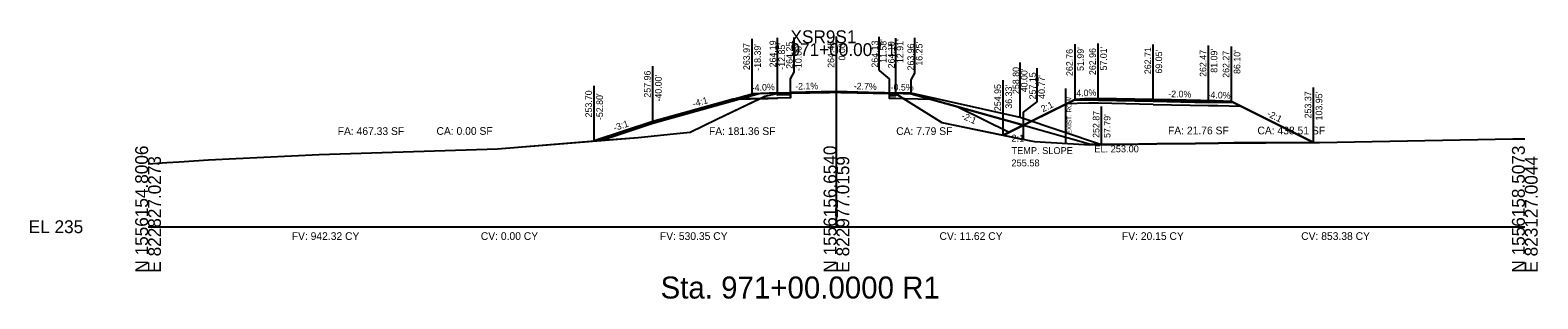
# Model space of a CAD drawing. Extents: x -26 to 823017, y -16 to 1558356.
# Drawn here: x 1974.3 to 2302.8, y 1984.3 to 2042.8 of the extents above; entities that cross this region are included whole.
import ezdxf

# ---------------------------------------------------------------- set-up
doc = ezdxf.new("R2010")
doc.units = 0
for name, color, linetype in [('1', 7, 'Continuous'), ('ASPHALT_19MM1', 7, 'Continuous'), ('ASPHALT_9_5MM1', 7, 'Continuous'), ('CONST_DCH', 7, 'Continuous'), ('CONST_LV3', 7, 'Continuous'), ('Draft_XS_Grid', 7, 'Continuous'), ('Draft_XS_Text', 7, 'Continuous'), ('DTM_CORRIDOR', 7, 'Continuous'), ('DTM_P_FINISHED_GRADE2', 7, 'Continuous'), ('DTM_X_GROUND', 7, 'Continuous'), ('SLOPE_STAKES_FILL', 7, 'Continuous'), ('X_PROFILES_1', 7, 'Continuous'), ('X_TRANS_EOP', 7, 'Continuous'), ('XS_CELL', 7, 'Continuous'), ('XS_M_SHAPES_EARTHWORK', 7, 'Continuous'), ('XS_P_ASPHALT', 7, 'Continuous'), ('XS_P_DR_GRAVEL', 7, 'Continuous'), ('XS_P_GROUND', 7, 'Continuous'), ('XS_P_NULL_POINT', 7, 'Continuous'), ('XS_P_SHOULDER', 7, 'Continuous'), ('XS_P_SUBGRADE_GRANULAR', 7, 'Continuous'), ('XS_P_SUBGRADE_LEVELING', 7, 'Continuous'), ('XS_P_SUBGRADE_MILLING', 7, 'Continuous'), ('XS_P_SUBGRADE_UNDERCUT', 7, 'Continuous'), ('XS_P_TX_CLEARZONE', 7, 'Continuous'), ('XS_P_TX_FS_BS', 7, 'Continuous'), ('XS_SHEET_EW_TX_AREA', 7, 'Continuous'), ('XS_SHEET_EW_TX_VOLUME', 7, 'Continuous'), ('XS_X_ROW', 7, 'Continuous')]:
    doc.layers.add(name, color=color, linetype=linetype)

msp = doc.modelspace()

# ---------------------------------------------------------------- linework, layer by layer
at = {"layer": '1'}
for points in [[(2140, 2029.12), (2140, 2028.95), (2137.15, 2028.9), (2137.15, 2029.06), (2140, 2029.12)], [(2161.58, 2029.01), (2161.58, 2029.01), (2161.58, 2028.84), (2161.58, 2028.84), (2161.58, 2028.84), (2162.91, 2028.81), (2162.91, 2028.81), (2162.91, 2028.97), (2161.58, 2029.01)]]:
    msp.add_lwpolyline(points, dxfattribs=at)
at = {"layer": 'ASPHALT_19MM1'}
for points in [[(2140, 2028.95), (2140, 2028.75), (2137.15, 2028.69), (2137.15, 2028.9), (2140, 2028.95)], [(2161.58, 2028.84), (2161.58, 2028.84), (2161.58, 2028.63), (2161.58, 2028.63), (2161.58, 2028.63), (2162.91, 2028.6), (2162.91, 2028.6), (2162.91, 2028.81), (2161.58, 2028.84)], [(2207.01, 2027.58), (2219.05, 2027.34), (2231.09, 2027.1), (2231.09, 2027.3), (2219.05, 2027.55), (2207.01, 2027.79), (2207.01, 2027.58)]]:
    msp.add_lwpolyline(points, dxfattribs=at)
at = {"layer": 'ASPHALT_9_5MM1'}
for points in [[(2140, 2029.25), (2140, 2029.12), (2137.15, 2029.06), (2137.15, 2029.19), (2140, 2029.25)], [(2161.58, 2029.13), (2161.58, 2029.13), (2161.58, 2029.01), (2161.58, 2029.01), (2161.58, 2029.01), (2162.91, 2028.97), (2162.91, 2028.97), (2162.91, 2029.1), (2161.58, 2029.13)]]:
    msp.add_lwpolyline(points, dxfattribs=at)
at = {"layer": 'CONST_LV3'}
for points in [[(2110, 2022.96), (2127.49, 2027.82), (2127.49, 2027.82)], [(2150, 2029.45), (2164, 2029.17)], [(2166.25, 2029.08), (2164, 2029.17), (2164, 2029.17)], [(2186.33, 2019.95), (2194.95, 2024.25), (2201.99, 2027.76), (2204.95, 2027.87), (2207.01, 2027.96)], [(2190.63, 2022.08), (2190.63, 2022.08), (2202.01, 2027.76), (2202.91, 2027.79), (2207.03, 2027.95), (2209.88, 2027.9), (2219.06, 2027.71), (2226.52, 2027.33), (2231.1, 2027.1), (2233.9, 2027.19), (2236.12, 2027.27), (2244.36, 2023.16), (2253.96, 2018.37), (2254.53, 2018.38), (2255.25, 2018.38), (2255.29, 2018.38), (2297.37, 2019.19), (2300, 2019.17)], [(2253.96, 2018.37), (2236.8, 2026.93), (2236.12, 2027.27)], [(2000, 2013.74), (2004.11, 2014), (2006.78, 2014.16), (2013.17, 2014.56), (2037.32, 2015.77), (2076.15, 2016.99), (2096.48, 2018.64), (2096.83, 2018.67), (2098.66, 2018.82)]]:
    msp.add_lwpolyline(points, dxfattribs=at)
at = {"layer": 'DTM_P_FINISHED_GRADE2'}
msp.add_lwpolyline([(2098.66, 2018.82), (2110, 2022.6), (2133.15, 2029.03), (2137.15, 2029.19), (2140, 2029.25), (2150, 2029.45), (2161.58, 2029.13), (2162.91, 2029.1), (2166.25, 2028.96), (2188.91, 2022.67), (2190.63, 2022.1)], dxfattribs=at)
at = {"layer": 'DTM_X_GROUND'}
for points in [[(2000, 2013.74), (2004.11, 2014), (2006.78, 2014.16), (2013.17, 2014.56), (2037.32, 2015.77), (2076.15, 2016.99), (2096.48, 2018.64), (2096.83, 2018.67), (2098.66, 2018.82), (2110, 2022.6), (2110, 2022.6), (2110, 2022.6), (2133.15, 2029.03), (2133.15, 2029.03), (2137.15, 2029.19), (2140, 2029.25), (2140, 2029.25), (2140, 2029.25), (2150, 2029.45), (2150, 2029.45), (2161.58, 2029.13), (2161.58, 2029.13), (2162.91, 2029.1), (2162.91, 2029.1), (2166.25, 2028.96), (2166.25, 2028.96), (2188.91, 2022.67), (2188.91, 2022.67), (2188.91, 2022.67), (2188.91, 2022.67), (2190.63, 2022.1), (2190.63, 2022.1), (2202.01, 2027.76), (2202.91, 2027.79), (2207.03, 2027.95), (2209.88, 2027.9), (2219.06, 2027.71), (2226.52, 2027.33), (2231.1, 2027.1), (2233.9, 2027.19), (2236.12, 2027.27), (2244.36, 2023.16), (2253.96, 2018.37), (2254.53, 2018.38), (2255.25, 2018.38), (2255.29, 2018.38), (2297.37, 2019.19), (2300, 2019.17)], [(2000, 2013.74), (2004.11, 2014), (2006.78, 2014.16), (2013.17, 2014.56), (2037.32, 2015.77), (2076.15, 2016.99), (2106.79, 2019.48), (2114.49, 2020.23), (2118.13, 2020.59), (2123.96, 2023.42), (2134.43, 2028.44), (2136.05, 2028.81), (2137.42, 2029.1), (2148.5, 2029.27), (2150.07, 2029.3), (2150.97, 2029.27), (2162.88, 2029.01), (2165.66, 2027.27), (2172.96, 2022.7), (2192.38, 2018.7), (2193.19, 2018.54), (2204.03, 2017.89), (2205.06, 2017.83), (2219.81, 2018.04), (2228.22, 2018.16), (2233.23, 2018.23), (2236.57, 2018.28), (2255.29, 2018.38), (2297.37, 2019.19), (2300, 2019.17)], [(2000, 2013.74), (2004.11, 2014), (2006.78, 2014.16), (2013.17, 2014.56), (2037.32, 2015.77), (2076.15, 2016.99), (2106.79, 2019.48), (2114.49, 2020.23), (2118.13, 2020.59), (2123.96, 2023.42), (2134.43, 2028.44), (2136.05, 2028.81), (2137.42, 2029.1), (2148.5, 2029.27), (2150.07, 2029.3), (2150.97, 2029.27), (2162.88, 2029.01), (2165.66, 2027.27), (2172.96, 2022.7), (2185.67, 2020.09), (2186.34, 2019.95), (2186.98, 2020.26), (2202.01, 2027.76), (2202.91, 2027.79), (2207.03, 2027.95), (2209.88, 2027.9), (2219.06, 2027.71), (2226.52, 2027.33), (2231.1, 2027.1), (2233.9, 2027.19), (2236.12, 2027.27), (2244.36, 2023.16), (2253.96, 2018.37), (2254.53, 2018.38), (2255.25, 2018.38), (2255.29, 2018.38), (2297.37, 2019.19), (2300, 2019.17)]]:
    msp.add_lwpolyline(points, dxfattribs=at)
at = {"layer": 'X_TRANS_EOP'}
msp.add_lwpolyline([(2207.01, 2027.79), (2219.05, 2027.55), (2231.09, 2027.3), (2231.09, 2027.47), (2219.05, 2027.71), (2207.01, 2027.96), (2207.01, 2027.79)], dxfattribs=at)
at = {"layer": 'XS_CELL'}
for p, q in [((2150, 2000), (2150, 2040)), ((2000, 2000), (2150, 2000)), ((2150, 2000), (2300, 2000))]:
    msp.add_line(p, q, dxfattribs=at)
at = {"layer": 'XS_M_SHAPES_EARTHWORK'}
for points in [[(2097.2, 2018.7), (2106.79, 2019.48), (2114.49, 2020.23), (2118.13, 2020.59), (2123.96, 2023.42), (2133.4, 2027.94), (2127.49, 2027.82), (2110, 2022.96)], [(2133.4, 2027.94), (2134.43, 2028.44), (2136.05, 2028.81), (2137.42, 2029.1), (2143.9, 2029.2), (2140, 2029.12), (2140, 2028.95), (2140, 2028.75), (2140, 2028.08), (2137.15, 2028.02), (2135.15, 2027.98)], [(2156.28, 2029.15), (2162.88, 2029.01), (2164.68, 2027.88), (2162.91, 2027.93), (2161.58, 2027.97), (2161.58, 2028.63), (2161.58, 2028.84), (2161.58, 2029.01), (2156.87, 2029.14)], [(2164.68, 2027.88), (2165.66, 2027.27), (2172.96, 2022.7), (2190.77, 2019.03), (2190.77, 2022.15), (2170.74, 2027.72), (2164.91, 2027.88)]]:
    msp.add_lwpolyline(points, close=True, dxfattribs=at)
at = {"layer": 'XS_P_ASPHALT'}
msp.add_lwpolyline([(2140, 2029.12), (2140, 2029.12), (2140, 2029.12), (2150, 2029.33), (2150, 2029.33), (2161.58, 2029.01), (2161.58, 2029.01), (2161.58, 2029.13), (2150, 2029.45), (2150, 2029.45), (2140, 2029.25), (2140, 2029.25), (2140, 2029.12)], dxfattribs=at)
at = {"layer": 'XS_P_DR_GRAVEL'}
for points in [[(2204.95, 2027.87), (2201.99, 2027.76), (2201.93, 2027.73), (2201.85, 2027.68), (2203.99, 2027.64), (2207.01, 2027.58), (2207.01, 2027.8), (2207.01, 2027.96), (2204.95, 2027.87)], [(2232.55, 2027.41), (2236.1, 2027.27), (2236.26, 2027.19), (2236.68, 2026.98), (2232.71, 2027.06), (2231.09, 2027.1), (2231.09, 2027.36), (2231.09, 2027.47), (2232.55, 2027.41)]]:
    msp.add_lwpolyline(points, dxfattribs=at)
at = {"layer": 'XS_P_GROUND'}
msp.add_line((2176.59, 2026.09), (2187.61, 2020.58), dxfattribs=at)
for points in [[(2097.2, 2018.7), (2110, 2022.96), (2110, 2022.96), (2131.61, 2028.97), (2131.61, 2028.97)], [(2207.79, 2017.87), (2190, 2023.8), (2190, 2023.8), (2166.25, 2029.08), (2166.25, 2029.08)], [(2190.77, 2022.15), (2166.25, 2028.96), (2166.25, 2028.96)], [(2201.99, 2027.76), (2186.33, 2019.95)], [(2236.1, 2027.27), (2253.95, 2018.37)], [(2253.96, 2018.37), (2253.96, 2018.37), (2236.57, 2018.28), (2236.57, 2018.28), (2236.57, 2018.28), (2233.23, 2018.23), (2228.22, 2018.16), (2228.22, 2018.16), (2219.81, 2018.04), (2219.81, 2018.04), (2207.79, 2017.87), (2207.79, 2017.87), (2207.79, 2017.87)], [(2253.96, 2018.37), (2253.96, 2018.37), (2236.57, 2018.28), (2236.57, 2018.28), (2236.57, 2018.28), (2233.23, 2018.23), (2228.22, 2018.16), (2228.22, 2018.16), (2219.81, 2018.04), (2219.81, 2018.04), (2207.79, 2017.87), (2207.79, 2017.87), (2207.79, 2017.87)]]:
    msp.add_lwpolyline(points, dxfattribs=at)
at = {"layer": 'XS_P_SHOULDER'}
for points in [[(2137.15, 2029.19), (2131.61, 2028.97)], [(2162.91, 2029.1), (2166.25, 2028.96)], [(2201.99, 2027.76), (2204.95, 2027.87), (2207.01, 2027.96)], [(2236.1, 2027.27), (2232.55, 2027.41), (2231.09, 2027.47)]]:
    msp.add_lwpolyline(points, dxfattribs=at)
at = {"layer": 'XS_P_SUBGRADE_GRANULAR'}
for points in [[(2127.49, 2027.82), (2135.15, 2027.98), (2135.15, 2027.98), (2137.15, 2028.02), (2137.15, 2028.02)], [(2140, 2028.08), (2137.15, 2028.02)], [(2140, 2028.08), (2140, 2029.25)], [(2161.58, 2027.97), (2161.58, 2029.13)], [(2162.91, 2027.93), (2161.58, 2027.97), (2161.58, 2027.97)], [(2170.74, 2027.72), (2164.91, 2027.88), (2164.91, 2027.88), (2162.91, 2027.93), (2162.91, 2027.93)], [(2207.01, 2026.91), (2205, 2026.95), (2199.98, 2026.75)], [(2219.05, 2026.67), (2207.01, 2026.91)], [(2219.05, 2026.67), (2231.09, 2026.43)], [(2231.09, 2026.43), (2233.09, 2026.39), (2238.07, 2026.29)]]:
    msp.add_lwpolyline(points, dxfattribs=at)
at = {"layer": 'XS_P_SUBGRADE_LEVELING'}
for points in [[(2140, 2029.12), (2140, 2029.12), (2148.5, 2029.3), (2148.5, 2029.3), (2150, 2029.33), (2150.07, 2029.32), (2150.97, 2029.3), (2150.97, 2029.3), (2161.58, 2029.01), (2161.58, 2029.01)], [(2140, 2029.12), (2140, 2029.12), (2143.9, 2029.2), (2143.9, 2029.2), (2148.5, 2029.27), (2150, 2029.29), (2150.07, 2029.3), (2150.97, 2029.27), (2156.28, 2029.15), (2156.28, 2029.15), (2161.58, 2029.01), (2161.58, 2029.01)]]:
    msp.add_lwpolyline(points, dxfattribs=at)
at = {"layer": 'XS_P_SUBGRADE_MILLING'}
msp.add_lwpolyline([(2161.58, 2029.04), (2161.58, 2029.04), (2161.58, 2029.01), (2161.58, 2029.01), (2161.58, 2029.01), (2156.28, 2029.15), (2156.28, 2029.15), (2150.97, 2029.27), (2150.07, 2029.3), (2150, 2029.29), (2148.5, 2029.27), (2143.9, 2029.2), (2143.9, 2029.2), (2140, 2029.12), (2140, 2029.12), (2140, 2029.14), (2140, 2029.14), (2148.5, 2029.27), (2148.5, 2029.27), (2150, 2029.29), (2150.07, 2029.3), (2150.97, 2029.27), (2150.97, 2029.27), (2161.58, 2029.04)], dxfattribs=at)
at = {"layer": 'XS_P_SUBGRADE_UNDERCUT'}
msp.add_lwpolyline([(2205.39, 2018), (2219.81, 2018.04), (2228.22, 2018.16), (2233.23, 2018.23), (2253.95, 2018.37), (2236.1, 2027.27), (2232.55, 2027.41), (2223.03, 2027.63), (2219.05, 2027.71), (2214.59, 2027.8), (2207.01, 2027.96), (2204.07, 2027.84), (2201.99, 2027.76), (2190.77, 2022.15)], close=True, dxfattribs=at)
at = {"layer": 'XS_P_TX_CLEARZONE'}
for p, q in [((2131.61, 2028.97), (2131.61, 2040.97)), ((2137.15, 2029.19), (2137.15, 2041.19)), ((2140.78, 2033.72), (2140.78, 2041.25)), ((2150, 2029.45), (2150, 2041.45)), ((2159.28, 2034.08), (2159.28, 2041.4)), ((2162.91, 2029.1), (2162.91, 2041.1)), ((2167.08, 2033.44), (2167.08, 2041.16)), ((2201.99, 2027.76), (2201.99, 2039.76)), ((2207.01, 2027.96), (2207.01, 2039.96)), ((2219.05, 2027.71), (2219.05, 2039.71)), ((2231.09, 2027.47), (2231.09, 2039.47)), ((2236.1, 2027.27), (2236.1, 2039.27)), ((2110, 2022.96), (2110, 2034.96)), ((2140, 2032.22), (2140.78, 2033.72)), ((2159.28, 2034.08), (2161.58, 2032.19)), ((2190, 2023.8), (2190, 2035.8)), ((2193.74, 2027.19), (2193.74, 2034.54)), ((2097.2, 2018.7), (2097.2, 2030.7)), ((2140, 2029.25), (2140, 2032.22)), ((2161.58, 2029.13), (2161.58, 2032.19)), ((2166.25, 2032.03), (2167.08, 2033.44)), ((2166.25, 2028.96), (2166.25, 2032.03)), ((2186.33, 2019.95), (2186.33, 2031.95)), ((2253.95, 2018.37), (2253.95, 2030.37)), ((2253.96, 2018.37), (2253.96, 2030.37)), ((2190.77, 2024.97), (2193.74, 2027.19)), ((2190.77, 2022.15), (2190.77, 2024.97)), ((2207.79, 2017.87), (2207.79, 2026.18))]:
    msp.add_line(p, q, dxfattribs=at)
at = {"layer": 'XS_X_ROW'}
msp.add_line((2200, 2018.13), (2200, 2030.13), dxfattribs=at)

# ---------------------------------------------------------------- texts
at = {"layer": 'CONST_DCH'}
for p in [(2137.07, 2029.07), (2139.92, 2029.13), (2149.92, 2029.33), (2161.5, 2029.01), (2162.83, 2028.98)]:
    msp.add_text('X', height=0.24, dxfattribs=at).set_placement(p)
at = {"layer": 'CONST_LV3'}
for p in [(2166.17, 2028.96), (2189.92, 2023.68), (2190.69, 2022.03), (2097.13, 2018.58), (2207.72, 2017.75), (2253.88, 2018.25)]:
    msp.add_text('X', height=0.24, dxfattribs=at).set_placement(p)
at = {"layer": 'Draft_XS_Grid'}
msp.add_text('-', height=0.0001, dxfattribs=at).set_placement((2000, 2000))
at = {"layer": 'Draft_XS_Text'}
msp.add_text('Sta. 971+00.0000 R1', height=4.8, dxfattribs=at).set_placement((2111.68, 1984.35))
at = {"layer": 'DTM_CORRIDOR'}
for p in [(2206.93, 2027.84), (2218.97, 2027.59), (2231.01, 2027.35)]:
    msp.add_text('X', height=0.24, dxfattribs=at).set_placement(p)
at = {"layer": 'SLOPE_STAKES_FILL'}
for p in [(2186.25, 2019.83), (2253.87, 2018.25)]:
    msp.add_text('X', height=0.24, dxfattribs=at).set_placement(p)
at = {"layer": 'X_PROFILES_1'}
msp.add_text('X', height=0.24, dxfattribs=at).set_placement((2253.88, 2018.25))
at = {"layer": 'XS_CELL'}
for s, p in [('XSR9S1', (2140, 2040)), ('971+00.00 / 1', (2140, 2037.2)), ('EL 235', (1974, 1998.6))]:
    msp.add_text(s, height=2.8, dxfattribs=at).set_placement(p)
for s, p in [('N 1556154.8006', (2000, 1990)), ('N 1556156.6540', (2150, 1990)), ('N 1556158.5073', (2300, 1990)), ('E 822827.0273', (2002.8, 1990)), ('E 822977.0159', (2152.8, 1990)), ('E 823127.0044', (2302.8, 1990))]:
    msp.add_text(s, height=2.8, rotation=90, dxfattribs=at).set_placement(p)
at = {"layer": 'XS_P_GROUND'}
for s, p in [('TEMP. SLOPE', (2188.14, 2015.85)), ('2:1', (2188.14, 2018.55)), ('255.58', (2188.14, 2013.15))]:
    msp.add_text(s, height=1.5, dxfattribs=at).set_placement(p)
at = {"layer": 'XS_P_NULL_POINT'}
for p in [(2190.69, 2022.03), (2097.13, 2018.58), (2186.25, 2019.83), (2253.87, 2018.25)]:
    msp.add_text('X', height=0.24, dxfattribs=at).set_placement(p)
at = {"layer": 'XS_P_SHOULDER'}
for p in [(2131.53, 2028.85), (2166.17, 2028.84), (2201.92, 2027.64), (2236.03, 2027.15)]:
    msp.add_text('X', height=0.24, dxfattribs=at).set_placement(p)
at = {"layer": 'XS_P_SUBGRADE_GRANULAR'}
msp.add_text('X', height=0.24, dxfattribs=at).set_placement((2109.92, 2022.84))
at = {"layer": 'XS_P_SUBGRADE_UNDERCUT'}
msp.add_text('EL. 253.00', height=1.5, dxfattribs=at).set_placement((2206.19, 2016.22))
at = {"layer": 'XS_P_TX_CLEARZONE'}
for s, p in [('264.19', (2136.87, 2034.72)), ('264.25', (2140.49, 2034.42)), ('264.45', (2149.52, 2034.63)), ("0.00'", (2151.92, 2036.24)), ('264.13', (2159.09, 2034.68)), ("11.58'", (2160.91, 2035.7)), ('264.10', (2162.67, 2034.51)), ("12.91'", (2164.58, 2035.66)), ('263.97', (2131.13, 2034.14)), ("-18.39'", (2133.53, 2033.99)), ("-12.85'", (2138.79, 2034.21)), ("-10.00'", (2142.41, 2033.93)), ('263.96', (2166.92, 2034.06)), ("16.25'", (2168.75, 2035.09)), ('262.76', (2201.51, 2032.85)), ("51.99'", (2203.91, 2033.95)), ('262.96', (2206.53, 2033.05)), ("57.01'", (2208.93, 2034.04)), ('262.71', (2218.57, 2033.25)), ("69.05'", (2220.97, 2033.37)), ('262.47', (2230.61, 2032.65)), ("81.09'", (2233.01, 2033.56)), ('262.27', (2235.62, 2032.45)), ("86.10'", (2238.02, 2033.29)), ('257.96', (2109.52, 2028.13)), ('258.80', (2189.84, 2028.92)), ("40.00'", (2191.63, 2029.3)), ("-40.00'", (2111.92, 2027.28)), ('254.95', (2185.85, 2025.2)), ("36.33'", (2188.25, 2025.72)), ('257.15', (2193.47, 2027.76)), ("40.77'", (2195.45, 2027.87)), ('253.70', (2096.72, 2023.82)), ("-52.80'", (2099.12, 2023.24)), ('253.37', (2253.47, 2023.62)), ('253.37', (2253.48, 2023.62)), ("103.95'", (2255.87, 2023.16)), ('252.87', (2207.31, 2019.36)), ("57.79'", (2209.71, 2019.34))]:
    msp.add_text(s, height=1.44, rotation=90, dxfattribs=at).set_placement(p)
at = {"layer": 'XS_P_TX_FS_BS'}
for s, rotation, p in [('-4.0%', 2.2906, (2131.56, 2029.56)), ('-2.1%', 1.1747, (2141.01, 2029.87)), ('-2.7%', 358.434, (2153.74, 2029.95)), ('-0.5%', 359.7096, (2161.79, 2029.7)), ('-4:1', 15.5253, (2118.9, 2026.06)), ('2:1', 26.526, (2195.02, 2024.94)), ('4.0%', 2.2723, (2202.28, 2028.37)), ('-2.0%', 358.8472, (2222.29, 2028.25)), ('-4.0%', 357.7061, (2230.83, 2028.08)), ('-2:1', 335.8194, (2177.08, 2023.67)), ('-2:1', 333.5005, (2243.67, 2024.17)), ('-3:1', 18.4332, (2101.69, 2020.83))]:
    msp.add_text(s, height=1.44, rotation=rotation, dxfattribs=at).set_placement(p)
at = {"layer": 'XS_SHEET_EW_TX_AREA'}
for s, p in [('FA: 467.33 SF', (2041.32, 2020)), ('CA: 0.00 SF', (2062.85, 2020.03)), ('FA: 181.36 SF', (2122.23, 2020)), ('CA: 7.79 SF', (2163.03, 2020)), ('FA: 21.76 SF', (2222.25, 2020.13)), ('CA: 438.51 SF', (2241.74, 2020.13))]:
    msp.add_text(s, height=1.68, dxfattribs=at).set_placement(p)
at = {"layer": 'XS_SHEET_EW_TX_VOLUME'}
for s, p in [('FV: 942.32 CY', (2031.31, 1997.12)), ('CV: 0.00 CY', (2072.51, 1997.12)), ('FV: 530.35 CY', (2111.54, 1997.12)), ('CV: 11.62 CY', (2172.46, 1997.12)), ('FV: 20.15 CY', (2212.21, 1997.12)), ('CV: 853.38 CY', (2251.27, 1997.12))]:
    msp.add_text(s, height=1.68, dxfattribs=at).set_placement(p)
at = {"layer": 'XS_X_ROW'}
msp.add_text('EXIST. ROW', height=1, rotation=90, dxfattribs=at).set_placement((2201.2, 2020.13))

doc.saveas('drawing.dxf')
